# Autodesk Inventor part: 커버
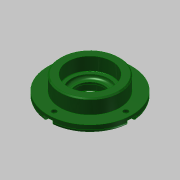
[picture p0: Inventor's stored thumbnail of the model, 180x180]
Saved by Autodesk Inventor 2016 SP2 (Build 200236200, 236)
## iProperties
Company: 한국ATC센터
Created: 2016-04
Part Number: 커버
Document SubType Name: Modeling
Designer: mdu
Density: 7.86 g/cm^3
Mass: 351.567 g
Surface Area: 161.165 cm^2
Volume: 44.7286 cm^3
Material: 강철, 연강
Appearance: 진녹색
Author: mdu
Revision Number: 1
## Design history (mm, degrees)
sketch "스케치1"
  geometry: C1 r 38 at (0, 0); 1 further point
  constraints: 1 centre point, 1 coincident
  dimensions: "d0" = 76 diameter of C1
extrude "돌출1" new body sketch "스케치1" distance "d1" = 7; taper "d2" = 0 deg
sketch "스케치2"
  geometry: C1 r 27 at (0, 0); 1 further point
  constraints: 1 centre point, 1 coincident
  dimensions: "d3" = 54 diameter of C1
extrude "돌출2" join sketch "스케치2" distance "d4" = 13; taper "d5" = 0 deg
sketch "스케치3"
  geometry: C1 r 20 at (0, 0); 1 further point
  constraints: 1 centre point, 1 coincident
  dimensions: "d6" = 40 diameter of C1
extrude "돌출3" join sketch "스케치3" distance "d7" = 5; taper "d8" = 0 deg
hole "구멍1" diameter "d11" = 25; stored, may be unused: countersink angle "d15" = 90 deg, drill point angle "d17" = 118 deg; dims "d9" = 10, "d10" = 10, "d12" = 6, "d13" = 32, "d14" = 8.3, "d16" = 8
hole "구멍2" diameter "d20" = 34; stored, may be unused: countersink angle "d24" = 90 deg, drill point angle "d26" = 0 deg; dims "d18" = 10, "d19" = 10, "d21" = 6, "d22" = 40, "d23" = 12, "d25" = 3
fillet "모깎기2" dims "d34" = 3
fillet "모깎기1" dims "d27" = 0.3
chamfer "모따기1" distance "d28" = 1; stored, may be unused: second distance "d29" = 2, angle "d30" = 45 deg
chamfer "모따기2" distance "d31" = 0.8; stored, may be unused: second distance "d32" = 2, angle "d33" = 30 deg
sketch "스케치4" dims "d35" = 65
  geometry: 3 further points
  constraints: 2 horizontal alignment, 1 coincident, 2 other
hole "구멍3" sketch "스케치4" at (32.5, 0) diameter "d36" = 4.5; stored, may be unused: countersink angle "d40" = 90 deg, drill point angle "d42" = 118 deg; dims "d37" = 6, "d38" = 8, "d39" = 4.4, "d41" = 13
sketch "스케치5"
  geometry: L1 (0, 4)-(5.5, 4); L2 (5.5, 4)-(5.5, -4); L3 (5.5, -4)-(0, -4); L4 (0, -4)-(0, 4); C1 r 2.25 at (0, 0) reference; C2 r 38 at (-32.5, 0) reference; 2 further points
  constraints: 8 end point, 3 horizontal, 2 parallel, 1 perpendicular, 1 tangent, 1 vertical alignment, 1 other
extrude "돌출4" cut sketch "스케치5" stored distance "d47" = 24.5; taper "d48" = 0 deg
node "솔리드1"
pattern_circular "원형 패턴1" dims angle "d44" = 360 deg
pattern_circular "원형 패턴2" dims angle "d50" = 360 deg
node "투영된 루프1"
